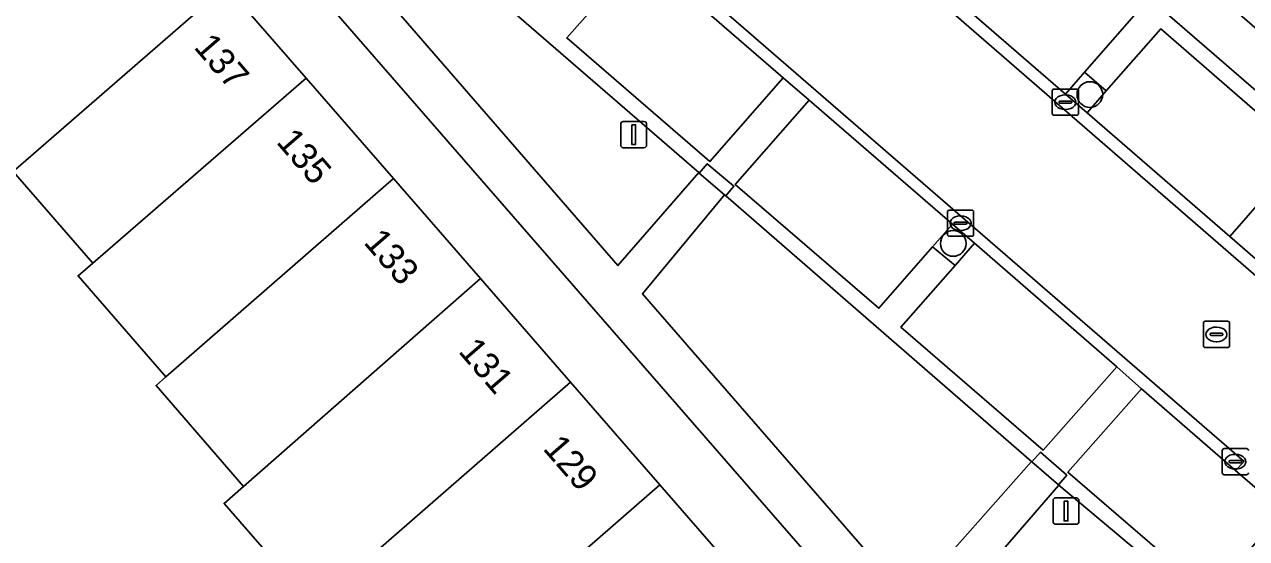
# Model space of a CAD drawing. Extents: x 161881 to 162523, y 381678 to 382381.
# Drawn here: x 161990.42 to 162037.06, y 382152.09 to 382171.7 of the extents above; entities that cross this region are included whole.
import ezdxf

# ---------------------------------------------------------------- set-up
doc = ezdxf.new("R2010")
doc.units = 0
for name, color, linetype in [('IMGEO_Boom', 7, 'Continuous'), ('IMGEO_Erf', 7, 'Continuous'), ('IMGEO_Groenvoorziening', 7, 'Continuous'), ('IMGEO_Kolk', 7, 'Continuous'), ('IMGEO_Lichtmast', 7, 'Continuous'), ('IMGEO_Pand', 7, 'Continuous'), ('IMGEO_Pand_nummerreeks', 7, 'Continuous'), ('IMGEO_Parkeervlak_open', 7, 'Continuous'), ('IMGEO_Rijbaan_lokaal_open', 7, 'Continuous'), ('IMGEO_Rioolput', 7, 'Continuous'), ('IMGEO_Voetpad_op_trap', 7, 'Continuous'), ('IMGEO_Voetpad_open', 7, 'Continuous')]:
    doc.layers.add(name, color=color, linetype=linetype)

msp = doc.modelspace()

# ---------------------------------------------------------------- linework, layer by layer
at = {"layer": 'IMGEO_Boom'}
for centre in [(162031.081, 382169.028), (162025.866, 382163.347)]:
    msp.add_circle(centre, 0.489, dxfattribs=at)
at = {"layer": 'IMGEO_Erf'}
for points in [[(162030.201, 382140.112), (161996.66, 382178.627), (161990.016, 382186.254), (161988.587, 382187.894), (161980.177, 382180.625), (161980.188, 382180.574), (161984.998, 382159.715), (161990.302, 382150.73)], [(161989.336, 382185.574), (161995.56, 382178.365), (161995.886, 382177.987), (161994.815, 382176.958), (161998.118, 382173.163), (162001.169, 382169.656), (162004.5, 382165.829), (162007.819, 382162.014), (162011.263, 382158.057), (162014.672, 382154.139), (162018.08, 382150.222)], [(162001.445, 382149.514), (161998.036, 382153.431), (161998.778, 382154.082), (161995.439, 382157.934), (161995.812, 382158.259), (161992.464, 382162.114), (161993.025, 382162.6), (161989.985, 382166.096)]]:
    msp.add_lwpolyline(points, dxfattribs=at)
at = {"layer": 'IMGEO_Groenvoorziening'}
for points in [[(162004.491, 382176.151), (162002.856, 382174.263), (162013.07, 382162.502), (162016.152, 382166.051)], [(162030.882, 382169.882), (162030.15, 382169.045), (162030.974, 382168.332), (162031.705, 382169.163)], [(162017.182, 382165.16), (162017.138, 382165.198), (162014.005, 382161.432), (162024.17, 382149.745), (162028.853, 382155.032)], [(162026.682, 382163.354), (162025.835, 382164.089), (162025.078, 382163.223), (162025.936, 382162.505)], [(162035.341, 382149.568), (162029.896, 382154.126), (162025.152, 382148.644), (162029.793, 382143.281)]]:
    msp.add_lwpolyline(points, close=True, dxfattribs=at)
at = {"layer": 'IMGEO_Kolk'}
for p, q in [((162029.647, 382168.31), (162029.647, 382169.162)), ((162029.722, 382169.236), (162030.574, 382169.236)), ((162030.135, 382169.016), (162030.16, 382169.016)), ((162030.648, 382169.162), (162030.648, 382168.31)), ((162029.906, 382168.73), (162029.906, 382168.742)), ((162030.344, 382168.693), (162029.946, 382168.693)), ((162029.949, 382168.779), (162030.347, 382168.779)), ((162030.158, 382168.456), (162030.133, 382168.456)), ((162030.39, 382168.742), (162030.39, 382168.73)), ((162030.574, 382168.236), (162029.722, 382168.236)), ((162025.644, 382163.694), (162025.644, 382164.546)), ((162025.719, 382164.62), (162026.571, 382164.62)), ((162026.132, 382164.4), (162026.157, 382164.4)), ((162026.645, 382164.546), (162026.645, 382163.694)), ((162025.903, 382164.114), (162025.903, 382164.126)), ((162026.341, 382164.077), (162025.943, 382164.077)), ((162025.946, 382164.163), (162026.344, 382164.163)), ((162026.155, 382163.84), (162026.13, 382163.84)), ((162026.387, 382164.126), (162026.387, 382164.114)), ((162026.571, 382163.62), (162025.719, 382163.62)), ((162036.135, 382154.598), (162036.135, 382155.45)), ((162036.21, 382155.524), (162037.062, 382155.524)), ((162036.394, 382155.018), (162036.394, 382155.03)), ((162036.832, 382154.981), (162036.434, 382154.981)), ((162036.437, 382155.067), (162036.835, 382155.067)), ((162036.623, 382155.304), (162036.648, 382155.304)), ((162036.878, 382155.03), (162036.878, 382155.018)), ((162037.062, 382154.524), (162036.21, 382154.524)), ((162036.646, 382154.744), (162036.621, 382154.744))]:
    msp.add_line(p, q, dxfattribs=at)
for points in [[(162029.647, 382168.31), (162029.647, 382169.162)], [(162029.722, 382169.236), (162030.574, 382169.236)], [(162030.648, 382169.162), (162030.648, 382168.31)], [(162030.574, 382168.236), (162029.722, 382168.236)], [(162025.644, 382163.694), (162025.644, 382164.546)], [(162025.719, 382164.62), (162026.571, 382164.62)], [(162026.645, 382164.546), (162026.645, 382163.694)], [(162026.571, 382163.62), (162025.719, 382163.62)], [(162036.135, 382154.598), (162036.135, 382155.45)], [(162036.21, 382155.524), (162037.062, 382155.524)], [(162037.062, 382154.524), (162036.21, 382154.524)]]:
    msp.add_lwpolyline(points, dxfattribs=at)
for centre, radius, start, end in [((162029.724, 382169.16), 0.0765, 91.552, 178.448), ((162029.724, 382169.16), 0.0765, 91.552, 178.448), ((162030.572, 382169.16), 0.0765, 1.552, 88.448), ((162030.572, 382169.16), 0.0765, 1.552, 88.448), ((162029.946, 382168.739), 0.0403, 85.8775, 175.7526), ((162029.943, 382168.729), 0.0366, 178.938, 274.7102), ((162030.347, 382168.736), 0.043, 264.8664, 352.4533), ((162030.351, 382168.741), 0.0386, 1.7309, 96.639), ((162029.724, 382168.312), 0.0765, 181.552, 268.448), ((162029.724, 382168.312), 0.0765, 181.552, 268.448), ((162030.572, 382168.312), 0.0765, 271.552, 358.448), ((162030.572, 382168.312), 0.0765, 271.552, 358.448), ((162025.721, 382164.544), 0.0765, 91.552, 178.448), ((162025.721, 382164.544), 0.0765, 91.552, 178.448), ((162026.569, 382164.544), 0.0765, 1.552, 88.448), ((162026.569, 382164.544), 0.0765, 1.552, 88.448), ((162025.943, 382164.123), 0.0403, 85.8775, 175.7526), ((162025.94, 382164.113), 0.0366, 178.938, 274.7102), ((162026.344, 382164.12), 0.043, 264.8664, 352.4533), ((162026.348, 382164.125), 0.0386, 1.7309, 96.639), ((162025.721, 382163.696), 0.0765, 181.552, 268.448), ((162025.721, 382163.696), 0.0765, 181.552, 268.448), ((162026.569, 382163.696), 0.0765, 271.552, 358.448), ((162026.569, 382163.696), 0.0765, 271.552, 358.448), ((162036.212, 382155.448), 0.0765, 91.552, 178.448), ((162036.212, 382155.448), 0.0765, 91.552, 178.448), ((162037.06, 382155.448), 0.0765, 1.552, 88.448), ((162037.06, 382155.448), 0.0765, 1.552, 88.448), ((162036.434, 382155.027), 0.0403, 85.8775, 175.7526), ((162036.431, 382155.017), 0.0366, 178.938, 274.7102), ((162036.835, 382155.024), 0.043, 264.8664, 352.4533), ((162036.839, 382155.029), 0.0386, 1.7309, 96.639), ((162036.212, 382154.6), 0.0765, 181.552, 268.448), ((162036.212, 382154.6), 0.0765, 181.552, 268.448), ((162037.06, 382154.6), 0.0765, 271.552, 358.448), ((162037.06, 382154.6), 0.0765, 271.552, 358.448)]:
    msp.add_arc(centre, radius, start, end, dxfattribs=at)
for centre, major_axis, ratio, start_param, end_param in [((162030.134, 382168.736), (-0.387, 0.002), 0.722429, 4.712389, 7.853982), ((162030.159, 382168.736), (-0.39, 0.002), 0.717154, 1.570796, 4.712389), ((162026.131, 382164.12), (-0.387, 0.002), 0.722429, 4.712389, 7.853982), ((162026.156, 382164.12), (-0.39, 0.002), 0.717154, 1.570796, 4.712389), ((162036.622, 382155.024), (-0.387, 0.002), 0.722429, 4.712389, 7.853982), ((162036.647, 382155.024), (-0.39, 0.002), 0.717154, 1.570796, 4.712389)]:
    msp.add_ellipse(centre, major_axis=major_axis, ratio=ratio, start_param=start_param, end_param=end_param, dxfattribs=at)
at = {"layer": 'IMGEO_Lichtmast'}
for p, q in [((162013.273, 382167.998), (162014.063, 382167.998)), ((162014.063, 382167.998), (162013.273, 382167.998)), ((162013.173, 382167.098), (162013.173, 382167.898)), ((162013.173, 382167.898), (162013.173, 382167.098)), ((162014.163, 382167.898), (162014.163, 382167.098)), ((162014.163, 382167.098), (162014.163, 382167.898)), ((162014.063, 382166.998), (162013.273, 382166.998)), ((162013.273, 382166.998), (162014.063, 382166.998)), ((162029.676, 382152.738), (162029.676, 382153.538)), ((162029.676, 382153.538), (162029.676, 382152.738)), ((162029.776, 382153.638), (162030.566, 382153.638)), ((162030.566, 382153.638), (162029.776, 382153.638)), ((162030.666, 382153.538), (162030.666, 382152.738)), ((162030.666, 382152.738), (162030.666, 382153.538)), ((162030.566, 382152.638), (162029.776, 382152.638)), ((162029.776, 382152.638), (162030.566, 382152.638))]:
    msp.add_line(p, q, dxfattribs=at)
for points in [[(162013.593, 382167.873), (162013.743, 382167.873), (162013.743, 382167.123), (162013.593, 382167.123), (162013.593, 382167.873)], [(162030.096, 382153.513), (162030.246, 382153.513), (162030.246, 382152.763), (162030.096, 382152.763), (162030.096, 382153.513)]]:
    msp.add_lwpolyline(points, dxfattribs=at)
for centre, start, end in [((162013.273, 382167.898), 90, 180), ((162013.273, 382167.898), 90, 180), ((162014.063, 382167.898), 0, 90), ((162014.063, 382167.898), 360, 90), ((162013.273, 382167.098), 180, 270), ((162013.273, 382167.098), 180, 270), ((162014.063, 382167.098), 270, 0), ((162014.063, 382167.098), 270, 0), ((162029.776, 382153.538), 90, 180), ((162029.776, 382153.538), 90, 180), ((162030.566, 382153.538), 0, 90), ((162030.566, 382153.538), 360, 90), ((162029.776, 382152.738), 180, 270), ((162029.776, 382152.738), 180, 270), ((162030.566, 382152.738), 270, 0), ((162030.566, 382152.738), 270, 0)]:
    msp.add_arc(centre, 0.1, start, end, dxfattribs=at)
at = {"layer": 'IMGEO_Pand'}
for points in [[(161998.118, 382173.163), (161994.815, 382176.958), (161995.886, 382177.987), (161995.56, 382178.365), (161990.236, 382173.705), (161987.617, 382171.413), (161985.858, 382169.874), (161985.395, 382169.468), (161986.163, 382168.584), (161988.921, 382165.41), (161989.039, 382165.274), (161989.985, 382166.096)], [(162001.169, 382169.656), (161998.118, 382173.163), (161989.985, 382166.096), (161993.025, 382162.6)], [(162004.5, 382165.829), (162001.169, 382169.656), (161993.025, 382162.6), (161992.464, 382162.114), (161995.812, 382158.259)], [(162007.819, 382162.014), (162004.5, 382165.829), (161995.812, 382158.259), (161995.439, 382157.934), (161998.778, 382154.082)], [(162011.263, 382158.057), (162007.819, 382162.014), (161998.778, 382154.082), (161998.036, 382153.431), (162001.445, 382149.514)], [(162014.672, 382154.139), (162011.263, 382158.057), (162001.445, 382149.514), (162004.853, 382145.596)], [(162018.08, 382150.222), (162014.672, 382154.139), (162004.853, 382145.596), (162008.262, 382141.679)]]:
    msp.add_lwpolyline(points, close=True, dxfattribs=at)
at = {"layer": 'IMGEO_Parkeervlak_open'}
for points in [[(162024.683, 382173.78), (162030.15, 382169.045), (162030.882, 382169.882), (162032.954, 382172.25), (162027.479, 382176.996)], [(162013.934, 382174.385), (162013.2, 382173.552), (162011.116, 382171.188), (162016.581, 382166.476), (162019.379, 382169.666)], [(162033.785, 382171.53), (162031.705, 382169.163), (162030.974, 382168.332), (162036.426, 382163.61), (162039.223, 382166.817)], [(162020.364, 382168.811), (162017.537, 382165.601), (162023.028, 382160.878), (162025.078, 382163.223), (162025.835, 382164.089)], [(162026.682, 382163.354), (162025.936, 382162.505), (162023.868, 382160.155), (162029.293, 382155.466), (162032.109, 382158.646)], [(162036.646, 382154.691), (162033.054, 382157.803), (162030.242, 382154.62), (162035.668, 382149.938), (162038.456, 382153.122)]]:
    msp.add_lwpolyline(points, close=True, dxfattribs=at)
at = {"layer": 'IMGEO_Rijbaan_lokaal_open'}
for points in [[(162023.729, 382174.608), (162018.255, 382179.355), (162017.419, 382180.08), (162011.989, 382184.789), (162011.011, 382185.637), (162005.61, 382190.321), (162004.744, 382191.044), (162004.578, 382191.195), (162004.274, 382190.846), (162005.488, 382189.784), (162024.055, 382173.714), (162042.512, 382157.689), (162042.811, 382158.044), (162042.829, 382158.065), (162037.387, 382162.778), (162036.426, 382163.61), (162030.974, 382168.332), (162030.15, 382169.045), (162024.683, 382173.78), (162024.348, 382174.07)], [(162001.899, 382185.403), (162000.705, 382186.422), (162000.438, 382186.65), (162000.135, 382186.301), (162000.395, 382186.065), (162000.428, 382186.035), (162001.236, 382185.346), (162005.021, 382182.115), (162006.67, 382180.667), (162007.638, 382179.817), (162013.107, 382175.099), (162013.934, 382174.385), (162019.379, 382169.666), (162020.364, 382168.811), (162025.835, 382164.089), (162026.682, 382163.354), (162032.109, 382158.646), (162033.054, 382157.803), (162036.646, 382154.691), (162036.967, 382155.028)]]:
    msp.add_lwpolyline(points, close=True, dxfattribs=at)
for points in [[(162001.899, 382185.403), (162036.967, 382155.028), (162036.646, 382154.691), (162038.456, 382153.122)], [(162042.512, 382157.689), (162024.055, 382173.714)]]:
    msp.add_lwpolyline(points, dxfattribs=at)
at = {"layer": 'IMGEO_Rioolput'}
for p, q in [((162035.413, 382159.452), (162035.413, 382160.304)), ((162035.488, 382160.378), (162036.34, 382160.378)), ((162035.901, 382160.158), (162035.926, 382160.158)), ((162036.414, 382160.304), (162036.414, 382159.452)), ((162035.672, 382159.872), (162035.672, 382159.884)), ((162036.11, 382159.835), (162035.712, 382159.835)), ((162035.715, 382159.921), (162036.113, 382159.921)), ((162035.924, 382159.598), (162035.899, 382159.598)), ((162036.156, 382159.884), (162036.156, 382159.872)), ((162036.34, 382159.378), (162035.488, 382159.378))]:
    msp.add_line(p, q, dxfattribs=at)
for points in [[(162035.413, 382159.452), (162035.413, 382160.304)], [(162035.488, 382160.378), (162036.34, 382160.378)], [(162036.414, 382160.304), (162036.414, 382159.452)], [(162036.34, 382159.378), (162035.488, 382159.378)]]:
    msp.add_lwpolyline(points, dxfattribs=at)
for centre, radius, start, end in [((162035.49, 382160.302), 0.0765, 91.552, 178.448), ((162035.49, 382160.302), 0.0765, 91.552, 178.448), ((162036.338, 382160.302), 0.0765, 1.552, 88.448), ((162036.338, 382160.302), 0.0765, 1.552, 88.448), ((162035.712, 382159.881), 0.0403, 85.8775, 175.7526), ((162035.709, 382159.871), 0.0366, 178.938, 274.7102), ((162036.113, 382159.878), 0.043, 264.8664, 352.4533), ((162036.117, 382159.883), 0.0386, 1.7309, 96.639), ((162035.49, 382159.454), 0.0765, 181.552, 268.448), ((162035.49, 382159.454), 0.0765, 181.552, 268.448), ((162036.338, 382159.454), 0.0765, 271.552, 358.448), ((162036.338, 382159.454), 0.0765, 271.552, 358.448)]:
    msp.add_arc(centre, radius, start, end, dxfattribs=at)
for centre, major_axis, ratio, start_param, end_param in [((162035.9, 382159.878), (-0.387, 0.002), 0.722429, 4.712389, 7.853982), ((162035.925, 382159.878), (-0.39, 0.002), 0.717154, 1.570796, 4.712389)]:
    msp.add_ellipse(centre, major_axis=major_axis, ratio=ratio, start_param=start_param, end_param=end_param, dxfattribs=at)
at = {"layer": 'IMGEO_Voetpad_op_trap'}
for points in [[(162016.48, 382166.39), (162016.175, 382166.031), (162017.138, 382165.198), (162017.182, 382165.16), (162017.495, 382165.528)], [(162029.192, 382155.382), (162028.872, 382155.015), (162029.88, 382154.141), (162030.197, 382154.504)]]:
    msp.add_lwpolyline(points, close=True, dxfattribs=at)
at = {"layer": 'IMGEO_Voetpad_open'}
for points in [[(162058.69, 382153.142), (162034.901, 382173.742), (162007.715, 382197.353), (162002.15, 382202.152), (162001.003, 382200.728), (162001.87, 382200.001), (162006.547, 382195.968), (162007.937, 382194.769), (162008.089, 382194.637), (162014.192, 382189.336), (162015.213, 382188.449), (162026.877, 382178.317), (162027.903, 382177.426), (162030.56, 382175.118), (162039.593, 382167.298)], [(162025.152, 382148.644), (162029.896, 382154.126), (162029.88, 382154.141), (162028.872, 382155.015), (162028.853, 382155.032), (162024.17, 382149.745), (162014.005, 382161.432), (162017.138, 382165.198), (162016.175, 382166.031), (162016.152, 382166.051), (162013.07, 382162.502), (162002.856, 382174.263), (162004.491, 382176.151), (162004.468, 382176.171), (162003.503, 382177.001), (162003.438, 382177.057), (162001.926, 382175.294), (161993.031, 382185.565), (161993.312, 382185.812), (161991.197, 382187.619), (161990.016, 382186.254), (161996.66, 382178.627), (162030.201, 382140.112)], [(162004.491, 382176.151), (162016.152, 382166.051), (162016.175, 382166.031), (162016.48, 382166.39), (162017.495, 382165.528), (162017.182, 382165.16), (162028.853, 382155.032), (162028.872, 382155.015), (162029.192, 382155.382), (162030.197, 382154.504), (162029.88, 382154.141), (162029.896, 382154.126), (162035.341, 382149.568)], [(162039.593, 382167.298), (162030.56, 382175.118)], [(162035.668, 382149.938), (162030.242, 382154.62), (162033.054, 382157.803), (162032.109, 382158.646), (162029.293, 382155.466), (162023.868, 382160.155), (162025.936, 382162.505), (162025.078, 382163.223), (162023.028, 382160.878), (162017.537, 382165.601), (162020.364, 382168.811), (162019.379, 382169.666), (162016.581, 382166.476), (162011.116, 382171.188), (162013.2, 382173.552)], [(162032.954, 382172.25), (162030.882, 382169.882), (162031.705, 382169.163), (162033.785, 382171.53), (162039.223, 382166.817), (162036.426, 382163.61), (162037.387, 382162.778)]]:
    msp.add_lwpolyline(points, dxfattribs=at)

# ---------------------------------------------------------------- texts
at = {"layer": 'IMGEO_Pand_nummerreeks'}
for s, p in [('137', (161996.848, 382170.821)), ('135', (161999.997, 382167.202)), ('133', (162003.329, 382163.372)), ('131', (162006.947, 382159.215)), ('129', (162010.173, 382155.508))]:
    msp.add_text(s, height=1, rotation=310.8345, dxfattribs=at).set_placement(p)

doc.saveas('drawing.dxf')
